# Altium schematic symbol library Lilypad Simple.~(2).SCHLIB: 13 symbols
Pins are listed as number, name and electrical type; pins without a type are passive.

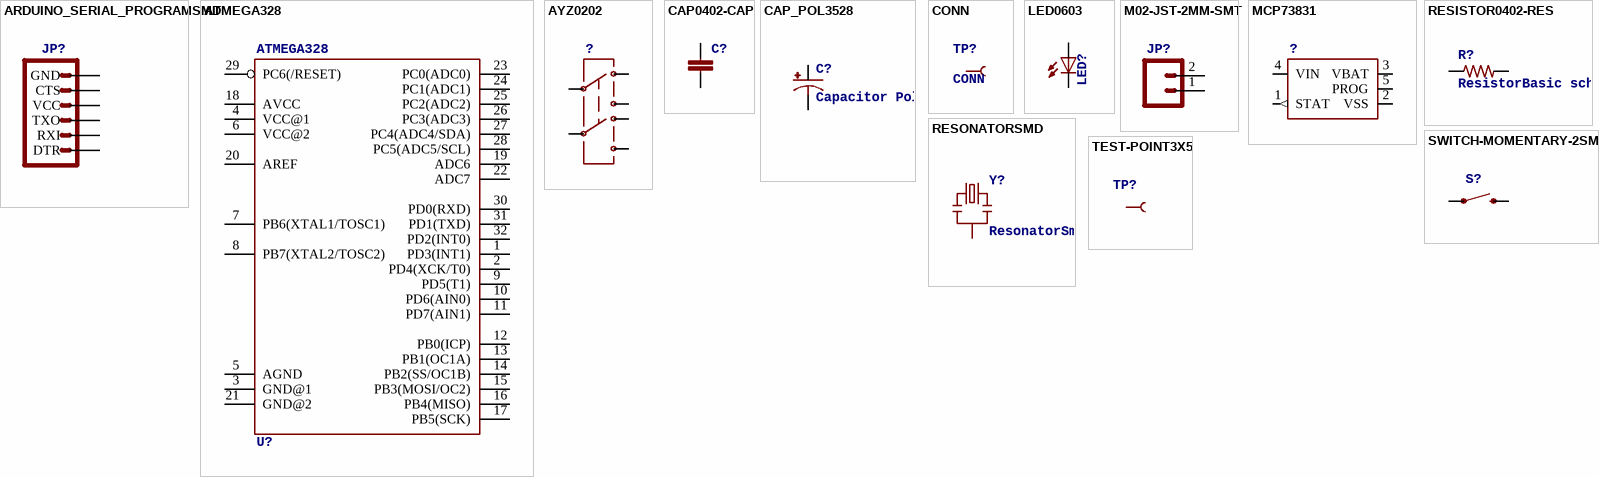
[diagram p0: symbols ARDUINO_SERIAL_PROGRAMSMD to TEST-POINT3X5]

## ARDUINO_SERIAL_PROGRAMSMD
designator JP?
footprint 1X06-SMD
pins: 1 DTR, 2 RXI, 3 TXO, 4 VCC, 5 CTS, 6 GND

## ATMEGA328
designator U?
footprint TQFP32-08
pins: 1 PD3(INT1), 2 PD4(XCK/T0), 3 GND@1, 4 VCC@1, 5 AGND, 6 VCC@2, 7 PB6(XTAL1/TOSC1), 8 PB7(XTAL2/TOSC2), 9 PD5(T1), 10 PD6(AIN0), 11 PD7(AIN1), 12 PB0(ICP), 13 PB1(OC1A), 14 PB2(SS/OC1B), 15 PB3(MOSI/OC2), 16 PB4(MISO), 17 PB5(SCK), 18 AVCC, 19 ADC6, 20 AREF, 21 GND@2, 22 ADC7, 23 PC0(ADC0), 24 PC1(ADC1), 25 PC2(ADC2), 26 PC3(ADC3), 27 PC4(ADC4/SDA), 28 PC5(ADC5/SCL), 29 PC6(/RESET), 30 PD0(RXD), 31 PD1(TXD), 32 PD2(INT0)

## AYZ0202
designator ?  (value not drawn)
footprint AYZ0202
pins: 1 3, 2, 3 1, 4 6, 5, 6 4

## CAP0402-CAP
designator C?  (value not drawn)
footprint 0402-CAP
pins: 1, 2

## CAP_POL3528
designator C?, comment Capacitor PolarizedThese are standard SMD and PTH capacitors. Normally 10uF, 47uF, and 100uF in electrolytic and tantalum varieties. Always verify the external diameter of the through hole cap, it varies with capacity, voltage, and manufacturer. The EIA devices should be standard.
footprint EIA3528
pins: A +, C -

## CONN
designator TP?
footprint PAD.03X.05
pins: P$1 1

## LED0603
designator LED?  (value not drawn)
footprint LED-0603
pins: A, C

## M02-JST-2MM-SMT
designator JP?  (value not drawn)
footprint JST-2-SMD
pins: 1, 2

## MCP73831
designator ?  (value not drawn)
footprint SOT23-5
pins: 1 STAT (out), 2 VSS (power), 3 VBAT (power), 4 VIN (power), 5 PROG

## RESISTOR0402-RES
designator R?, comment ResistorBasic schematic elements and footprints for 0603, 1206, and PTH resistors.
footprint 0402-RES
pins: 1, 2

## RESONATORSMD
designator Y?, comment ResonatorSmall SMD resonator. This is the itty bitty 10/20MHz resonators with built in caps. CSTCE10M0G55 and CSTCE20M0V53. Footprint has been reviewed closely but hasn't been tested yet.
footprint RESONATOR-SMD
pins: 1, 2, 3

## SWITCH-MOMENTARY-2SMD-2
designator S?
footprint TACTILE_SWITCH_SMD-2
pins: 1 2, 2 1

## TEST-POINT3X5
designator TP?
footprint PAD.03X.05
pins: P$1 1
